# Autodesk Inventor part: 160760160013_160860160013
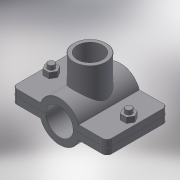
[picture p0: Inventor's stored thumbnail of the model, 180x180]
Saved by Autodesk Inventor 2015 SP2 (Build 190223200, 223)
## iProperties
Created: 2017-05
Part Number: 160760160013_160860160013
Material: Generic
Description: PLASSON SADDLE 160-1.1/4"
Document SubType Name: Modeling
Designer: KIM
Density: 1 g/cm^3
Appearance: Default
Author: KIM
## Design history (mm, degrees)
derived "16076.ipt"
feature "Solid1::16076.ipt"
feature "Solid2::16076.ipt"
tag "TaggingFeature1"
body "Solid1"
other parameters: "d0" = 176, "d1" = 223, "d4" = 145, "d5" = 0, "d6" = 11.15, "d7" = 223, "d8" = 0.1, "d10" = 0, "d11" = 1.6, "d14" = 50.6376, "d20" = 1.6, "d23" = 1.6, "d36" = 15, "d37" = 12, "d38" = 88, "d39" = 0, "d40" = 3, "d41" = 5, "d42" = 0, "d44" = 3, "d45" = 0, "d46" = 1.6, "d51" = 117, "d52" = 38.952, "d53" = 25, "d54" = 0, "d55" = 32, "d57" = 0, "d58" = 172.8, "d60" = 0, "d62" = 15, "d63" = 12, "d66" = 121, "B_" = 32, "G_" = 38.952, "A_" = 117, "L_" = 223, "L_1" = 145, "l_2" = 25
